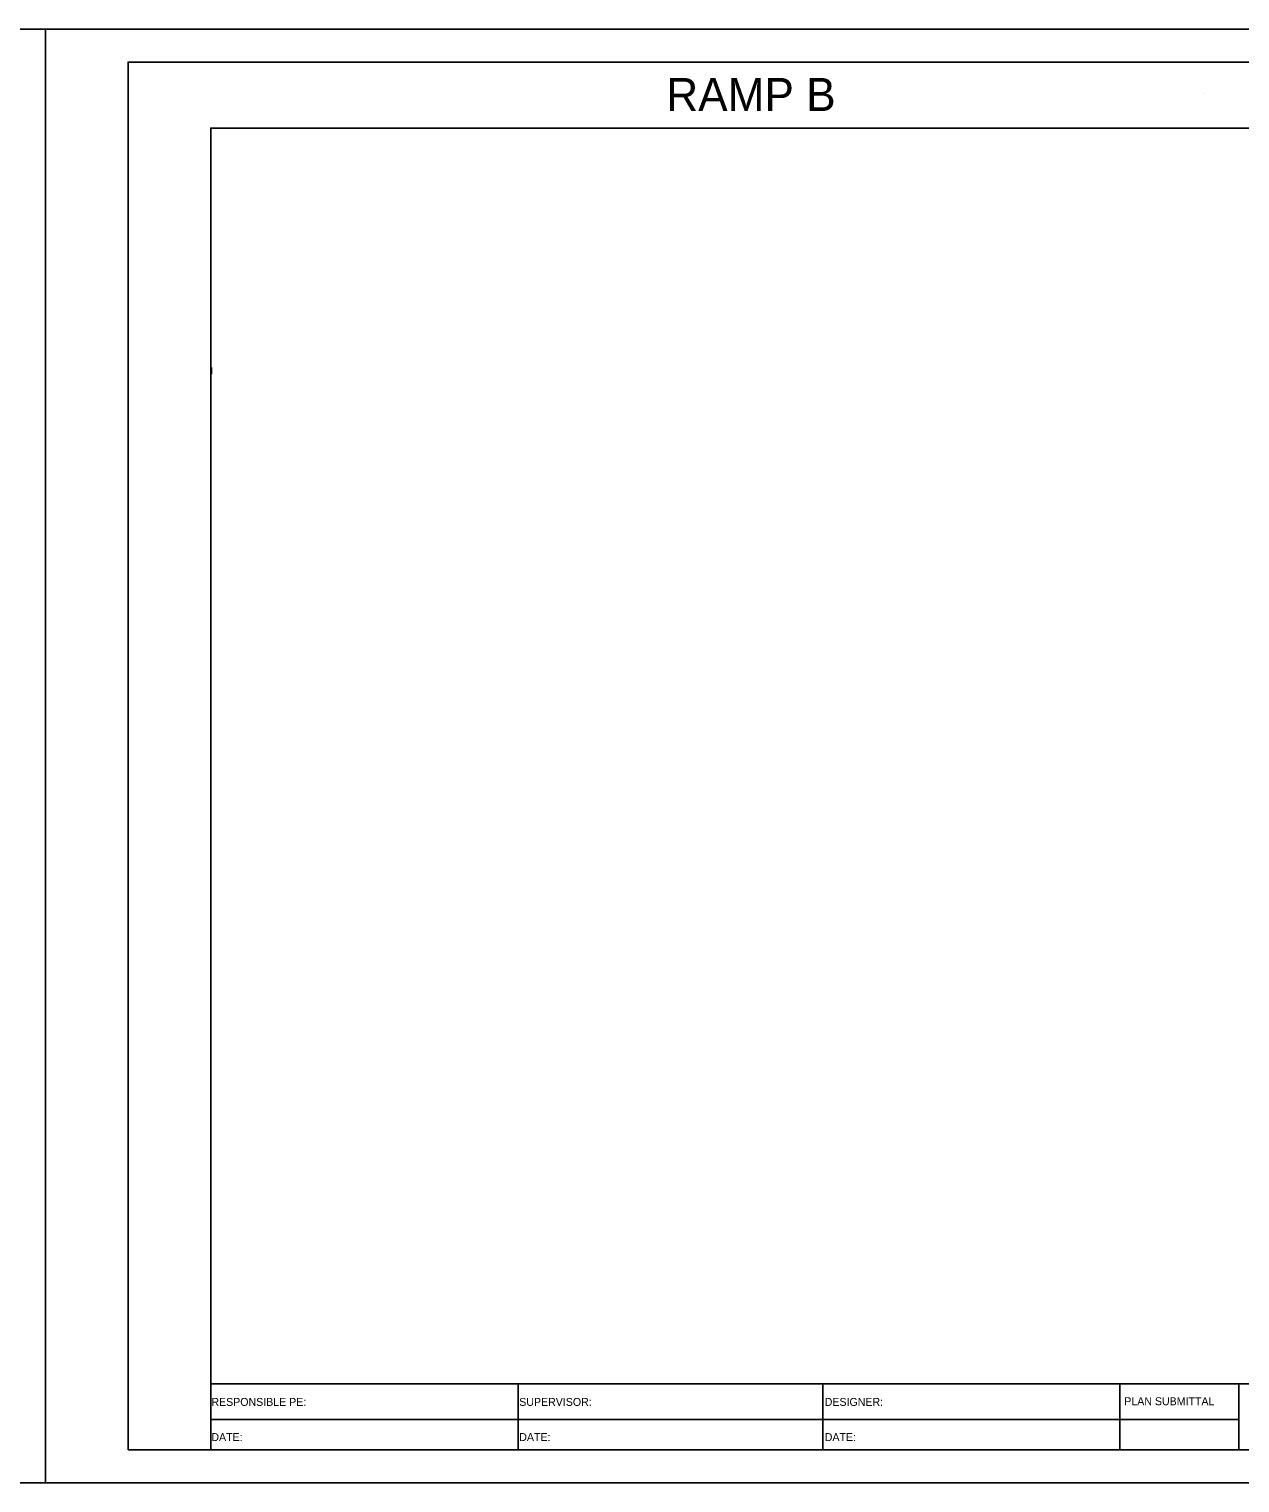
# Model space of a CAD drawing. Extents: x 1797478 to 1805176, y 246529 to 250952.
# Drawn here: x 1804493.5 to 1804676.8, y 250064.4 to 250284.4 of the extents above; entities that cross this region are included whole.
import ezdxf

# ---------------------------------------------------------------- set-up
doc = ezdxf.new("R2010")
doc.units = 0
for name, color, linetype in [('2', 7, 'Continuous'), ('ANNO-SHT', 7, 'Continuous'), ('ANNO-TXT', 7, 'Continuous'), ('AXIS', 7, 'Continuous'), ('DRAINAGE', 7, 'Continuous'), ('Level 1', 7, 'Continuous'), ('Level 62', 7, 'Continuous'), ('SHT-BDR', 7, 'Continuous'), ('SHT-BNDRY', 7, 'Continuous')]:
    doc.layers.add(name, color=color, linetype=linetype)

# ---------------------------------------------------------------- blocks, each defined once
blk = doc.blocks.new('SC47208')
at = {"layer": 'Level 1'}
blk.add_line((0, 0), (0, 0), dxfattribs=at)

msp = doc.modelspace()

# ---------------------------------------------------------------- linework, layer by layer
at = {"layer": '2'}
msp.add_lwpolyline([(1804521.12, 250233.21), (1804521.1, 250232.21)], dxfattribs=at)
msp.add_lwpolyline([(1804521.12, 250233.21), (1804521.1, 250232.21)], dxfattribs=at)
at = {"layer": 'AXIS'}
msp.add_line((1804521, 250189.42), (1804521, 250189.43), dxfattribs=at)
at = {"layer": 'Level 62'}
for points in [[(1804156, 250064.42), (1804496, 250064.42), (1804496, 250284.42), (1804156, 250284.42)], [(1804496, 250064.42), (1804836, 250064.42), (1804836, 250284.42), (1804496, 250284.42)]]:
    msp.add_lwpolyline(points, close=True, dxfattribs=at)
at = {"layer": 'SHT-BDR'}
msp.add_lwpolyline([(1804521, 250079.43), (1804821, 250079.43), (1804821, 250269.43), (1804521, 250269.43)], close=True, dxfattribs=at)
at = {"layer": 'SHT-BNDRY'}
for p, q in [((1804521, 250069.42), (1804521, 250079.43)), ((1804567.52, 250079.43), (1804567.52, 250069.42)), ((1804613.67, 250069.42), (1804613.67, 250079.43)), ((1804658.59, 250069.42), (1804658.59, 250079.43)), ((1804676.63, 250069.42), (1804676.63, 250079.43)), ((1804521, 250074.03), (1804676.63, 250074.03))]:
    msp.add_line(p, q, dxfattribs=at)
msp.add_lwpolyline([(1804508.5, 250069.42), (1804831, 250069.42), (1804831, 250279.42), (1804508.5, 250279.42)], close=True, dxfattribs=at)

# ---------------------------------------------------------------- block references
at = {"layer": 'DRAINAGE', "xscale": 0.2, "yscale": 0.20000000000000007, "rotation": -116.41666666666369}
msp.add_blockref('SC47208', (1804671.32, 250274.62), dxfattribs=at)
msp.add_blockref('SC47208', (1804671.32, 250274.62), dxfattribs=at)

# ---------------------------------------------------------------- texts
at = {"layer": 'ANNO-SHT'}
msp.add_text('                 RAMP B                 ', height=4.9995, rotation=360, dxfattribs=at).set_placement((1804558.38, 250272.02))
at = {"layer": 'ANNO-TXT'}
for s, p in [('RESPONSIBLE PE:', (1804521.1, 250076.08)), ('SUPERVISOR:', (1804567.7, 250076.08)), ('DESIGNER:', (1804613.94, 250076.08)), ('PLAN SUBMITTAL', (1804659.28, 250076.18)), ('DATE:', (1804521.1, 250070.76)), ('DATE:', (1804567.7, 250070.76)), ('DATE:', (1804613.94, 250070.76))]:
    msp.add_text(s, height=1.2, rotation=360, dxfattribs=at).set_placement(p)

doc.saveas('drawing.dxf')
